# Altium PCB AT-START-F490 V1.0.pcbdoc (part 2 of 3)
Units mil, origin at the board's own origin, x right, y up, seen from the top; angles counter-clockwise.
Board outline 15424.54 x 3536.36 mil, 2 copper layers (Top Layer, Bottom Layer); 130 components, 126 nets, 528 pads, 715 vias.
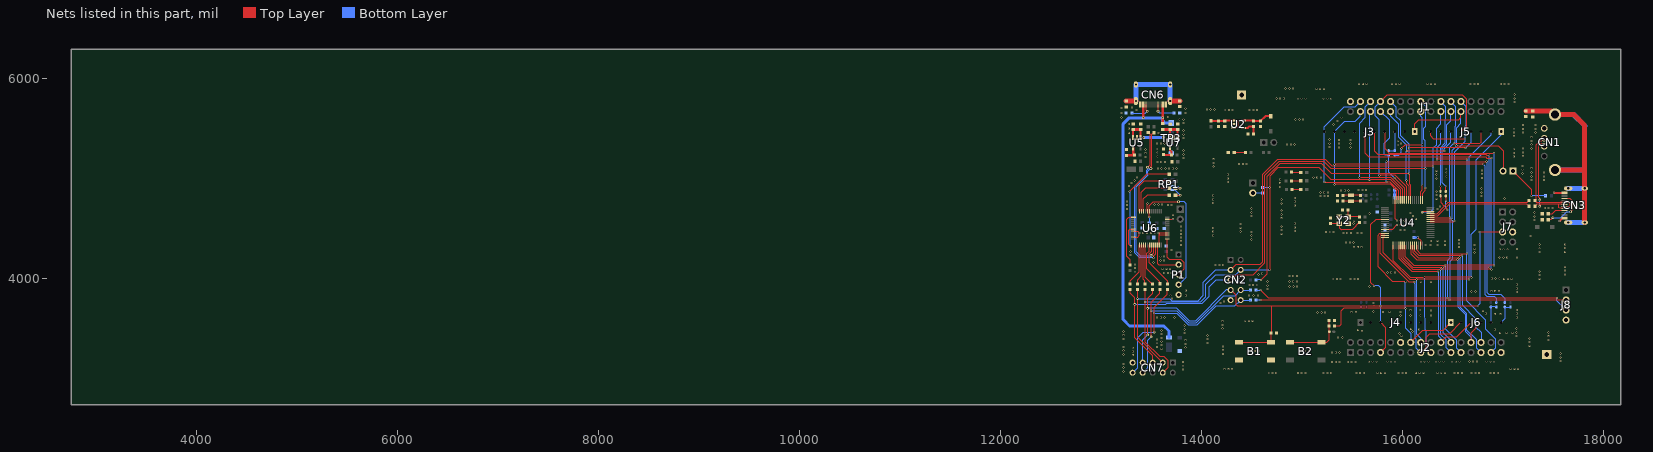
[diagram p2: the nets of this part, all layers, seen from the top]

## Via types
v1: diameter 19.68, hole 11.81, Top Layer to Bottom Layer, 622 vias
v2: diameter 19.69, hole 11.81, Top Layer to Bottom Layer, 42 vias
v3: diameter 23.62, hole 11.81, Top Layer to Bottom Layer, 17 vias
v4: diameter 27.56, hole 13.78, Top Layer to Bottom Layer, 15 vias
v5: diameter 19.7, hole 11.81, Top Layer to Bottom Layer, 10 vias
v6: diameter 24, hole 12, Top Layer to Bottom Layer, 7 vias
v7: diameter 27.56, hole 15.75, Top Layer to Bottom Layer, 2 vias

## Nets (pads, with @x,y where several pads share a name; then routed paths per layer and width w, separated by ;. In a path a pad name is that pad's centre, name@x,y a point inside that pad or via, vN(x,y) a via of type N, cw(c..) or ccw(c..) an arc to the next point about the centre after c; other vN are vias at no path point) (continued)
$1N336: LD2.1 RP1.7 | length 125.3
  Top Layer w6: LD2.1@13742.62,4903.16 13786.17,4903.16 v4(13786.58,4903.56)
  Bottom Layer w6: RP1.7@13713.41,4922.99 13767.15,4922.99 v4(13786.58,4903.56)
$1N337: LD1.1 RP1.8 | length 147.5
  Top Layer w6: LD1.1@13742.62,4833.56 v4(13790.58,4833.56)
  Bottom Layer w6: RP1.8@13713.41,4887.56 13736.58,4887.56 v4(13790.58,4833.56)
$1N361: C15.1 C16.1 C18.1 C19.1 F2.2 U5.1 U5.3 U7.1 U7.3 | length 730.4
  Top Layer w20: U5.3@13320.15,5405.9 13320.15,5484.86 C18.1@13321.15,5485.86 ; U5.1@13395.15,5405.9 C19.1@13395.15,5485.86 ; U7.3@13689.34,5407.9 C15.1@13689.34,5486.07 ; U7.1@13764.34,5407.9 C16.1@13764.34,5487.9
  Top Layer w30: C18.1@13321.15,5485.86 C19.1@13395.15,5485.86 ; F2.2@13617.56,5487.94 13689.58,5487.94 C16.1@13764.31,5487.94
  Bottom Layer w30: v4(13427.14,5405.91) 13616.74,5405.91 v4(13617.84,5407.02)
$1N396: R50.1 R51.1 U5.4 | length 160.1
  Top Layer w25: R51.1@13254.58,5231.06 13332.58,5231.06 R50.1@13335.08,5233.56 13320.15,5248.49 U5.4@13320.15,5305.9
$1N467: R43.1 R49.1 U7.4 | length 163.5
  Top Layer w20: R49.1@13616.92,5236.02 R43.1@13702.92,5236.02 13702.92,5267.02 13689.34,5280.6 U7.4@13689.34,5307.9
$2N290: C3.1 D2.1 R1.2 U2.5 | length 294.6
  Top Layer w20: U2.5@14417.58,5577.54 14513.92,5577.53 R1.2@14518.58,5572.87 C3.1@14590.58,5572.87 14638.07,5620.36 D2.1@14690.58,5620.36
$2N291: R1.1 R2.2 U2.4 | length 180.7
  Top Layer w20: U2.4@14417.58,5502.54 14462.55,5502.53 14477.89,5517.88 R1.1@14518.58,5517.87 R2.2@14518.08,5444.56
$2N326: LED1.1 R3.2 | length 110.5
  Top Layer w10: LED1.1@14328.62,5259.36 14328.83,5259.56 R3.2@14439.08,5259.56
$2N337: C1.1 C2.1 F1.2 U2.1 U2.3 | length 370.1
  Top Layer w6: U2.3@14317.58,5502.54 14346.55,5502.53 14360.58,5516.56 14360.58,5565.56 14348.6,5577.53 U2.1@14317.58,5577.54
  Top Layer w20: F1.2@14096.38,5575.88 14099.38,5572.88 C1.1@14172.58,5572.87 C2.1@14232.58,5572.87 14237.24,5577.53 U2.1@14317.58,5577.54
$2N360: B2.3 B2.4 R5.2 R6.1 R7.1 | length 593.1
  Top Layer w10: B2.4@14883.61,3367.74 14886.02,3370.14 15196.06,3370.14 15246.16,3370.14 15270.58,3394.57 15270.58,3471.68 R6.1@15273.45,3474.57 15269.08,3478.95 R5.2@15269.08,3530.57 R7.1@15269.08,3586.57
$2N488: LED3.1 R14.1 | length 90.1
  Top Layer w10: R14.1@14898.69,4976.21 14899.25,4976.77 LED3.1@14988.53,4976.77
$2N489: LED2.1 R13.1 | length 88.5
  Top Layer w10: R13.1@14900.08,4890.56 14900.3,4890.77 LED2.1@14988.53,4890.77
$2N490: LED4.1 R15.1 | length 90.4
  Top Layer w10: R15.1@14898.69,5062.21 14900.14,5060.77 LED4.1@14988.53,5060.77
$2N12490: JP2.1 R54.1 | length 462.3
  Top Layer w6: JP2.1@17103.58,5073.56 17287.58,4889.56 v1(17287.58,4827.56)
  Bottom Layer w6: v1@17286.58,4828.56 v1(17287.58,4827.56) R54.1@17426.26,4827.56
$3N199: J6.5 R34.2 R35.2 | length 211.5
  Bottom Layer w6: R34.2@16880.58,3721.16 R34.2@16881.06,3720.68 ; J6.5@16883.88,3566.57 16883.88,3717.86 R34.2@16881.06,3720.68 ; R35.2@16936.58,3720.68 R34.2@16881.06,3720.68
$3N200: J6.6 R36.2 R37.2 | length 225.1
  Bottom Layer w6: J6.6@16983.88,3566.57 17020.58,3603.26 R36.2@17020.58,3720.16 17075.97,3720.16 R37.2@17076.58,3719.57
$3N264: J3.3 R38.1 R39.1 | length 249.4
  Bottom Layer w6: R38.1@15864.58,5277.05 15923.93,5277.05 R39.1@15924.58,5277.69 15923.88,5278.39 J3.3@15923.88,5466.56
$4N238: C25.2 R26.2 Y2.3 | length 181.2
  Top Layer w6: C25.2@15460.58,4684.56 15460.58,4617.72 Y2.3@15459.89,4617.03 15460.35,4616.56 R26.2@15573.08,4616.56
$4N239: C26.2 R27.2 Y2.1 | length 366.6
  Top Layer w6: C26.2@15283.58,4549.56 15372.73,4549.56 Y2.1@15373.26,4550.1 15373.26,4511.88 15394.58,4490.56 15501.08,4490.56 R27.2@15573.08,4562.56
$4N333: C24.2 R23.2 Y1.2 | length 173.4
  Top Layer w6: C24.2@15411.08,4773.56 15412.08,4774.56 R23.2@15584.08,4774.56
$4N335: C23.2 R22.2 Y1.1 | length 171
  Top Layer w6: C23.2@15411.08,4832.56 Y1.1@15487.58,4832.56 R22.2@15582.08,4832.56
$4N462: JP1.2 R31.1 | length 99.2
  Bottom Layer w6: JP1.2@14511.57,4856.56 14610.08,4856.56 R31.1@14610.58,4856.06
ATLINK_5V: CN6.A4B9 CN6.B4A9 D3.2 F2.1 TP3.1 | length 3381.4
  Top Layer w25: v4(13421.92,5604.02) 13422.08,5604.17 CN6.B4A9@13422.08,5735.27 ; v4(13614.56,5604.02) v4@13615.03,5604.49 ; CN6.A4B9@13615.08,5735.27 13615.08,5604.49 13615.08,5549.73 F2.1@13616.58,5548.23
  Bottom Layer w30: D3.2@13676.62,3415.32 13676.58,3482.57 13626.58,3532.57 13283.81,3532.57 13220.92,3595.45 13220.92,5543.59 13281.34,5604.02 v4(13421.92,5604.02) v4(13614.56,5604.02) 13614.56,5573.39 13636.92,5551.02 TP3.1@13699.92,5551.02
ATLK_RX: CN2.10 CN7.10 R10.2 R48.1 | length 2143.2
  Top Layer w6: v3(13530.58,3470.57) v2(13530.58,3660.57) 13530.58,3718.57 13660.58,3848.57 R48.1@13660.58,3893.07
  Bottom Layer w6: CN7.10@13315.34,3067.01 13365.92,3117.59 13365.92,3416.01 13420.47,3470.57 v3(13530.58,3470.57) ; v2(13530.58,3660.57) 13752.58,3660.57 13868.58,3544.57 13960.58,3544.57 14148.58,3732.57 14333.65,3732.57 CN2.10@14390.92,3789.84 ; CN2.10@14390.97,3789.89 14391.26,3790.2 R10.2@14490.52,3790.2
ATLK_TX: CN2.8 CN7.8 R9.2 R47.1 | length 2063.7
  Top Layer w6: v3(13499.34,3423.01) 13499.34,3769.34 13586.34,3856.34 R47.1@13586.34,3886.01
  Bottom Layer w6: CN7.8@13415.35,3067.01 13463.92,3115.58 13463.92,3387.58 v3(13499.34,3423.01) ; v3(13498.58,3682.57) 13756.58,3682.57 13876.58,3562.57 13950.58,3562.57 14222.58,3834.57 14335.65,3834.57 CN2.8@14390.92,3889.84 14392.02,3888.74 R9.2@14486.73,3888.74
BOOT0/PF11: CN2.4 CN7.4 J1.28 R31.2 R45.1 U4.60 | length 5618.1
  Top Layer w6: R45.1@13438.34,3888.01 13438.34,3376.8 13583.12,3232.01 13623.92,3232.01 13665.92,3190.01 13665.92,3117.59 CN7.4@13615.34,3067.01 ; v2(14678.58,4090.57) 14678.58,5022.56 14760.58,5104.56 15174.58,5104.56 15292.58,4986.56 v1(15675.45,4986.56) 15884.58,4986.56 15984.67,4886.47 U4.60@15984.67,4787.08
  Bottom Layer w6: v3(13438.58,3770.57) 13994.58,3770.57 14044.58,3820.57 14044.58,3945.57 14141.58,4042.57 14343.65,4042.57 CN2.4@14390.92,4089.84 v2(14678.58,4090.57) ; R31.2@14610.58,4911.06 v5(14678.73,4911.06) ; v1(15675.45,4986.56) 15675.58,4986.82 15675.58,5657.99 J1.28@15683.44,5665.86
CC1: CN6.A5 R56.1 | length 231.5
  Top Layer w6: v4@13567.58,5669.56 v4(13567.77,5669.77) CN6.A5@13567.77,5735.27
  Bottom Layer w6: v4(13567.77,5669.77) 13585.98,5651.56 R56.1@13725.92,5651.56
CC2: CN6.B5 R57.1 | length 230.4
  Top Layer w6: CN6.B5@13449.67,5735.27 13449.67,5681.47 v4(13461.58,5669.56)
  Bottom Layer w6: R57.1@13309.24,5651.56 13443.58,5651.56 v4(13461.58,5669.56)
EGND: C30.2 CN1.SH1 CN1.SH2 CN3.13 CN3.14 CN3.15 CN3.16 R59.1 | length 3841.4
  Top Layer w50: C30.2@17229.58,5670.56 17485.51,5670.56 CN1.SH1@17519.93,5636.15 17706.99,5636.15 17815.88,5527.27 17815.88,5089.56 ; CN1.SH2@17519.93,5084.97 17811.28,5084.97 17815.88,5089.56 ; CN3.15@17815.88,4561.47 CN3.16@17815.88,4901.66 17815.88,5089.56
  Bottom Layer w50: CN1.SH2@17519.93,5084.97 17812.82,5084.97 17815.88,5081.92 ; CN1.SH1@17519.93,5636.15 17703.99,5636.15 17816.58,5523.56 17815.88,5522.86 17815.88,5081.92 ; CN3.13@17651.28,4561.47 CN3.15@17815.88,4561.47 CN3.16@17815.88,4901.66 ; CN3.14@17651.28,4901.66 CN3.16@17815.88,4901.66 ; CN3.16@17815.88,4901.66 17815.88,5081.92
EGND2: C29.2 CN6.13 CN6.14 CN6.15 CN6.16 R55.1 | length 863.4
  Top Layer w50: R55.1@13250.58,5771.56 13348.17,5771.56 CN6.14@13348.48,5771.27 ; CN6.13@13688.67,5771.27 13688.82,5771.12 C29.2@13784.58,5771.12
  Bottom Layer w50: CN6.14@13348.48,5771.27 CN6.16@13348.48,5935.86 CN6.15@13688.67,5935.86 CN6.13@13688.67,5771.27
FCC1: CN3.A5 R17.1 | length 176.6
  Top Layer w6: R17.1@17452.24,4649.56 17494.58,4649.56 17527.38,4682.36 CN3.A5@17615.28,4682.36
FCC2: CN3.B5 R16.1 | length 457.9
  Top Layer w6: R16.1@17453.24,4589.56 17478.58,4589.56 v6(17499.58,4610.56) ; CN3.B5@17615.28,4800.47 17669.67,4800.47 17692.58,4777.56 17692.58,4685.56 v6(17675.58,4668.56)
  Bottom Layer w6: v6(17499.58,4610.56) 17576.58,4610.56 17634.58,4668.56 v6(17675.58,4668.56)
FD+: CN1.3 CN3.A6 CN3.B6 R18.2 | length 1102.9
  Top Layer w11.2: R18.2@17321.58,4776.56 R18.2@17321.4,4776.4 ; CN1.3@17413.23,5399.94 17382.46,5369.16 17369.73,5369.16 17334.38,5333.81 17334.38,4793.36 R18.2@17321.58,4780.56 17321.4,4780.4 R18.2@17321.4,4776.4 ; CN3.A6@17615.28,4721.77 17658.78,4721.77 17666.58,4729.56 17666.58,4752.56 17658.08,4761.06 CN3.B6@17615.28,4761.06 17579.12,4761.06 17577.88,4759.81 17337.99,4759.81 R18.2@17321.4,4776.4
FD-: CN1.2 CN3.A7 CN3.B7 R19.2 | length 1109.5
  Top Layer w11.2: R19.2@17321.24,4717.56 17321.24,4724.87 17338.98,4742.61 17367.52,4742.61 ; v6(17367.52,4722.62) 17367.52,4742.61 ; v6(17367.58,4786.56) 17367.58,4804.56 17351.58,4820.56 17351.58,5326.68 17369.16,5344.27 17390.15,5344.27 CN1.2@17413.23,5321.19 ; 17559.58,4742.5 17559.58,4710.56 17568.08,4702.06 CN3.B7@17615.28,4702.06 ; CN3.A7@17615.28,4741.36 17579.12,4741.36 17577.88,4742.61 17367.52,4742.61
  Bottom Layer w11.2: v6(17367.52,4722.62) v6@17367.52,4786.51
GND: B1.3 B1.4 C1.2 C2.2 C3.2 C4.2 C5.2 C6.2 C7.2 C8.2 C9.2 C10.2 C11.2 C12.2 C13.1 C14.2 C15.2 C16.2 C17.2 C18.2 C19.2 C22.2 C23.1 C24.1 C25.1 C26.1 C27.1 C28.1 C29.1 C30.1 CN1.4 CN2.9 CN3.A1B12 CN3.B1A12 CN6.A1B12 CN6.B1A12 CN7.9 D4.2 J1.31 J2.12 J2.31 J3.7 J4.6 J4.7 J7.6 J8.4 LED1.2 P1.5 R2.1 R7.2 R16.2 R17.2 R49.2 R51.2 R55.2 R56.2 R57.2 R59.2 T1.1 T2.1 TP3.4 U2.2 U4.12 U4.31 U4.63 U5.2 U6.8 U6.20 U6.23 U6.35 U6.39 U6.40 U6.47 U7.2 Y2.2 Y2.4 | length 1321.8
  Top Layer w8: U4.63@15925.62,4787.08 15925.62,4604.52 v1(15946.58,4583.56) ; v1(16154.11,4412.03) 16181.52,4384.61 U4.31@16181.52,4334.34
  Top Layer w9: U4.12@15827.2,4491.81 15900.82,4491.81 v1(15946.58,4537.56)
  Top Layer w10: U6.23@13324.5,4417.1 13365.11,4417.1 13383.58,4435.56 v1(13383.58,4458.56) 13365.98,4476.16 U6.20@13324.5,4476.16 ; U6.8@13462.3,4673.02 13462.58,4673.3 v1(13462.58,4750.56) ; U6.35@13580.41,4338.36 13580.41,4449.2 ; U6.39@13659.15,4436.8 13592.81,4436.8 13580.41,4449.2 ; U6.40@13659.15,4456.48 13659.06,4456.56 v1(13573.04,4456.56) 13580.41,4449.2 ; U6.47@13659.15,4594.27 13717.28,4594.27 v1(13717.58,4594.56)
  Top Layer w20: v1(17508.58,4862.56) 17513.58,4857.56 17614.47,4857.56 CN3.B1A12@17615.28,4858.36 ; v1(17564.58,4575.56) 17593.58,4604.56 CN3.A1B12@17615.28,4604.56
  Bottom Layer w20: C4.2@15924.08,4884.56 15924.58,4884.06 C5.2@15924.58,4834.56 15924.58,4797.56 ; C6.2@16115.6,4414.83 16118.4,4412.03 v1(16154.11,4412.03)
  other v1: 14670.58,3064.57 14707.81,3064.57 14745.04,3064.57 14960.58,3064.57 14997.81,3064.57 15035.04,3064.57 15217.58,3064.57 15254.81,3064.57 15292.04,3064.57 15542.58,3064.57 15579.81,3064.57 15617.04,3064.57 15962.58,3064.57 15999.81,3064.57 16037.04,3064.57 16518.58,3064.57 16555.81,3064.57 16593.04,3064.57 16689.58,3064.57 16726.81,3064.57 16764.04,3064.57 16876.58,3064.57 16913.81,3064.57 16951.04,3064.57 15752.58,3065.57 15789.81,3065.57 15827.04,3065.57 16134.58,3065.57 16171.81,3065.57 16209.04,3065.57 16350.58,3065.57 16387.81,3065.57 16425.04,3065.57 13225.58,3079.57 13817.58,3098.57 14230.58,3101.57 14267.81,3101.57 14305.04,3101.57 17077.58,3105.57 17114.81,3105.57 17152.04,3105.57 13225.58,3116.8 13817.58,3135.8 13225.58,3154.03 13817.58,3173.03 15300.58,3174.57 15337.81,3174.57 15375.04,3174.57 15457.58,3174.57 15494.81,3174.57 15532.04,3174.57 15666.58,3175.57 15703.81,3175.57 15741.04,3175.57 15851.58,3175.57 15888.81,3175.57 15926.04,3175.57 16185.58,3175.57 16222.81,3175.57 16260.04,3175.57 16334.58,3175.57 16371.81,3175.57 16409.04,3175.57 16495.58,3175.57 16532.81,3175.57 16570.04,3175.57 16838.58,3175.57 16875.81,3175.57 16913.04,3175.57 16667.58,3176.57 16704.81,3176.57 16742.04,3176.57 17572.58,3182.57 17572.58,3219.8 13317.58,3240.57 13224.58,3248.57 14213.58,3253.57 17572.58,3257.03 15300.58,3268.57 15337.81,3268.57 15375.04,3268.57 13317.58,3277.8 14494.29,3281.57 14531.52,3281.57 14568.75,3281.57 14996.57,3281.56 15033.8,3281.56 15071.04,3281.56 13224.58,3285.8 14213.58,3290.8 13603.58,3304.57 13317.58,3315.03 13840.58,3315.57 13224.58,3323.03 13558.58,3322.57 14213.58,3328.03 17268.58,3334.57 13603.58,3341.8 13840.58,3352.8 13558.58,3359.8 14059.58,3363.57 17268.58,3371.8 13603.58,3379.03 13840.58,3390.03 17457.58,3393.1 13558.58,3397.03 14059.58,3400.8 13224.58,3402.57 17268.58,3409.03 13603.58,3413.57 15360.58,3417.57 15406.97,3417.57 17457.58,3430.33 17138.58,3430.57 15992.58,3433.57 14059.58,3438.03 13224.58,3439.8 13603.58,3450.8 15971.58,3455.57 13829.58,3460.57 16974.58,3463.57 17036.92,3463.57 17098.36,3463.57 17138.58,3467.8 17457.58,3467.57 13224.58,3477.03 16100.58,3477.57 15597.58,3479.57 13603.58,3488.03 15560.58,3493.57 16920.58,3497.35 13829.58,3497.8 16168.58,3498.57 16088.58,3503.57 14210.58,3504.57 17138.58,3505.03 13829.58,3535.03 14210.58,3541.8 14210.58,3579.03 14436.58,3583.57 14473.81,3583.57 14511.04,3583.57 13559.11,3616.57 13596.34,3616.57 13633.58,3616.57 13731.58,3617.57 17139.58,3617.57 15981.58,3634.57 16285.58,3635.57 16081.58,3636.57 16178.58,3636.57 16920.58,3648.57 16975.48,3648.57 17139.58,3654.8 15156.58,3664.57 15193.81,3664.57 15231.04,3664.57 15495.58,3668.57 15540.58,3668.57 15807.58,3671.57 15981.58,3672.25 15873.58,3672.57 15715.58,3674.92 16285.58,3686.21 16081.58,3688.73 16178.58,3689.83 17139.58,3692.03 15715.58,3760.57 14191.58,3761.57 14223.58,3774.57 13707.58,3807.57 13844.58,3834.9 14474.58,3836.57 14517.81,3836.57 14562.28,3836.57 13693.58,3837.57 17139.58,3868.57 16690.58,3873.57 16727.81,3873.57 16887.58,3877.57 16924.81,3877.57 16962.04,3877.57 13844.58,3886.57 14656.58,3899.57 17139.58,3905.8 14877.58,3924.57 14914.81,3924.57 14952.04,3924.57 15674.58,3925.57 14656.58,3936.8 14476.58,3939.57 14513.81,3939.57 14551.04,3939.57 17139.58,3943.03 16183.58,3971.57 16286.58,3971.57 14656.58,3974.03 14876.58,3974.57 14913.81,3974.57 14951.04,3974.57 15312.58,4000.57 15349.81,4000.57 15387.04,4000.57 15484.58,4000.57 15521.81,4000.57 15559.04,4000.57 17363.58,4001.1 17014.11,4001.57 17051.34,4001.57 17088.58,4001.57 16890.58,4003.57 16927.81,4003.57 16965.04,4003.57 14876.58,4030.57 14913.81,4030.57 14951.04,4030.57 17363.58,4038.33 14569.58,4042.57 17619.58,4046.1 14605.58,4054.57 13630.11,4059.57 13667.34,4059.57 13704.58,4059.57 15851.89,4065.14 15889.12,4065.14 15926.35,4065.14 13339.58,4071.57 17363.58,4075.57 17619.58,4083.33 13613.11,4100.56 13650.34,4100.56 13687.58,4100.56 13339.58,4108.8 17619.58,4120.56 14142.58,4137.56 14179.81,4137.56 14217.04,4137.56 13339.58,4146.03 13524.58,4164.56 13593.58,4183.56 13627.58,4183.56 16969.58,4215.56 17006.81,4215.56 17044.04,4215.56 17142.58,4215.56 13593.58,4220.8 13627.58,4221.63 13294.58,4237.56 16717.58,4262.33 17363.58,4268.1 17621.58,4270.1 13294.58,4272.69 13703.58,4289.56 16970.58,4295.56 17007.81,4295.56 17045.04,4295.56 17142.58,4296.56 16717.58,4299.56 17363.58,4305.33 17621.58,4307.33 15519.58,4315.56 15556.81,4315.56 15594.04,4315.56 16564.58,4318.33 16281.58,4336.56 16348.58,4336.96 16426.58,4336.56 16717.58,4336.8 13797.58,4338.56 16228.58,4338.56 17363.58,4342.56 17621.58,4344.56 16564.58,4352.56 15440.58,4362.56 15477.81,4362.56 15515.04,4362.56 13797.58,4375.8 16283.58,4378.56 16426.58,4379.17 16348.58,4379.56 16564.58,4387.8 14500.58,4393.56 13797.58,4413.03 17274.58,4427.56 14500.58,4430.8 14117.58,4432.56 13796.58,4446.56 14795.58,4449.56 13498.58,4456.56 13535.81,4456.56 15414.58,4456.56 15451.81,4456.56 15489.04,4456.56 13420.81,4458.56 13458.04,4458.56 14500.58,4468.03 15240.58,4468.56 15277.81,4468.56 15315.04,4468.56 14117.58,4469.8 14387.58,4471.56 14929.58,4476.56 13796.58,4483.8 14795.58,4486.8 14117.58,4507.03 14387.58,4508.8 14929.58,4513.8 13796.58,4521.03 14795.58,4524.03 15983.81,4537.56 16021.04,4537.56 14387.58,4546.03 14929.58,4551.03 15983.81,4583.56 16021.04,4583.56 17317.58,4586.56 16134.58,4598.56 14795.58,4604.56 17317.58,4623.8 14500.58,4625.56 16105.58,4625.56 13717.58,4638.57 14795.58,4641.8 16083.58,4655.56 17317.58,4661.03 14500.58,4662.8 14795.58,4679.03 13258.58,4697.56 16350.58,4697.56 14500.58,4700.03 17418.58,4706.56 17455.81,4706.56 17493.04,4706.56 16375.58,4722.56 14929.58,4732.56 13258.58,4734.8 13668.58,4735.56 13703.67,4735.56 13534.58,4741.56 13571.81,4741.56 13609.04,4741.56 14795.58,4752.56 14117.58,4754.56 14929.58,4769.8 13258.58,4772.03 14795.58,4789.8 14117.58,4791.8 16338.58,4797.56 17018.04,4799.56 14929.58,4807.03 16790.58,4825.33 15186.58,4825.56 15223.81,4825.56 15261.04,4825.56 14117.58,4829.03 16338.58,4834.8 15185.58,4859.56 15222.81,4859.56 15260.04,4859.56 16790.58,4862.56 16338.58,4872.03 15390.58,4881.56 15427.81,4881.56 15465.04,4881.56 15564.58,4885.56 15601.81,4885.56 15639.04,4885.56 16790.58,4899.8 14784.58,4915.56 13278.58,4926.56 14784.58,4952.8 13305.58,4953.56 14262.58,4964.56 13332.58,4979.56 17286.58,4983.56 17410.58,4984.56 14784.58,4990.03 14262.58,5001.8 16342.58,5001.56 16792.58,5005.33 13357.58,5007.56 15115.58,5011.56 15152.81,5011.56 15190.04,5011.56 16437.58,5020.56 17286.58,5020.8 17410.58,5021.8 14262.58,5039.03 16342.58,5038.8 16792.58,5042.56 17196.58,5049.56 16437.58,5057.8 17286.58,5058.03 17410.58,5059.03 16342.58,5076.03 16792.58,5079.8 17196.58,5086.8 16437.58,5095.03 13567.58,5098.56 13604.81,5098.56 13642.04,5099.56 13678.58,5099.56 13715.81,5099.56 13753.04,5099.56 17286.58,5102.56 14118.58,5117.56 17196.58,5124.03 14375.58,5143.56 14412.81,5143.56 14450.04,5143.56 14118.58,5154.8 13562.58,5163.56 13599.81,5163.56 13637.04,5163.56 14118.58,5192.03 13821.58,5202.56 13444.58,5214.56 17109.58,5216.56 13560.58,5219.56 17201.58,5221.56 13821.58,5239.8 13444.58,5251.8 17109.58,5253.8 13560.58,5256.8 17201.58,5258.8 13821.58,5277.03 13444.58,5289.03 17109.58,5291.03 13560.58,5294.03 17201.58,5296.03 17286.58,5297.03 15370.58,5309.56 15483.58,5309.56 15276.58,5312.56 15959.58,5334.56 17286.58,5336.56 14853.58,5338.56 14890.81,5338.56 14928.04,5338.56 15370.58,5346.8 15483.58,5346.8 15987.58,5347.56 13559.58,5348.56 13596.81,5348.56 13634.04,5348.56 15276.58,5349.8 17286.58,5373.8 15959.58,5375.29 15370.58,5384.03 15483.58,5384.03 15276.58,5387.03 13820.58,5402.56 17286.58,5411.03 17110.58,5420.56 13820.58,5439.8 13572.58,5451.56 13277.58,5454.56 17202.58,5456.56 17324.58,5456.56 17110.58,5457.8 13820.58,5477.03 17202.58,5493.8 17324.58,5493.8 17110.58,5495.03 13277.58,5499.09 17202.58,5531.03 17324.58,5531.03 15313.58,5537.56 13277.19,5541.35 13821.58,5551.56 15356.58,5571.56 14938.58,5587.56 14975.81,5587.56 15013.04,5587.56 13779.58,5588.56 13821.58,5588.8 15395.58,5604.56 13204.58,5605.56 13669.58,5611.56 13840.57,5651.57 13204.58,5652.69 14480.58,5680.56 14517.81,5680.56 14555.04,5680.56 13355.58,5681.56 14237.58,5682.56 14274.81,5682.56 14312.04,5682.56 14054.58,5686.56 14091.81,5686.56 14129.04,5686.56 13840.57,5698.23 13203.58,5701.56 13309.79,5706.25 17114.58,5760.56 14960.58,5793.56 14997.81,5793.56 15035.04,5793.56 15217.58,5793.56 15254.81,5793.56 15292.04,5793.56 14745.58,5795.56 14782.81,5795.56 14820.04,5795.56 17114.58,5797.8 17114.58,5835.03 15144.58,5892.56 15181.81,5892.56 15219.04,5892.56 14838.58,5895.56 14875.81,5895.56 14913.04,5895.56 16680.58,5940.56 16717.81,5940.56 16755.04,5940.56 16980.58,5940.56 17017.81,5940.56 17055.04,5940.56 15569.58,5942.56 15606.81,5942.56 15644.04,5942.56 15898.58,5942.56 15935.81,5942.56 15973.04,5942.56 16249.58,5942.56 16286.81,5942.56 16324.04,5942.56
  other v5: 16831.58,3654.57 16803.58,3682.57 15553.58,4456.56 15595.31,4456.56 15981.58,4485.56 16020.01,4485.56 15514.58,4550.56 15521.58,4578.56 15671.58,4650.56
LD1: LD1.2 U6.10 | length 397.2
  Top Layer w6: U6.10@13422.92,4673.02 13422.92,4795.91 13460.58,4833.56 LD1.2@13681.62,4833.56
LD2: LD2.2 U6.11 | length 485.7
  Top Layer w6: U6.11@13403.24,4673.02 13403.24,4864.23 13442.17,4903.16 LD2.2@13681.62,4903.16
LD3: LD3.2 U6.12 | length 585.9
  Top Layer w6: U6.12@13383.56,4673.02 13383.56,4928.55 13427.58,4972.56 LD3.2@13681.42,4972.56 ; LD3.2@13681.62,4972.76 LD3.2@13681.42,4972.56 ; LD3.2@13695.42,4972.56 LD3.2@13681.42,4972.56
LD4: LD4.2 U6.19 | length 1244
  Top Layer w6: v1(13286.58,4872.56) 13456.37,5042.36 LD4.2@13681.62,5042.36 ; v3(13298.92,4324.02) 13275.92,4347.02 13275.92,4487.02 13284.76,4495.85 U6.19@13324.5,4495.85
  Bottom Layer w6: v1(13286.58,4872.56) 13286.34,4872.34 13286.34,4336.6 v3(13298.92,4324.02)
M-ATLK_RX: R48.2 U6.31 | length 479.5
  Top Layer w6: U6.31@13501.67,4338.36 13501.67,4272.34 13474.58,4245.24 13474.58,4165.44 13660.34,3979.68 R48.2@13660.34,3947.01
M-ATLK_TX: R47.2 U6.30 | length 454
  Top Layer w6: U6.30@13481.98,4338.36 13481.98,4276.65 13458.58,4253.24 13458.58,4099.26 13586.34,3971.49 R47.2@13586.34,3947.01
M-NRST: C22.1 P1.4 U6.7 | length 1403.3
  Top Layer w6: v3(13480.85,4617.02) 13481.98,4618.15 U6.7@13481.98,4673.02 ; U6.7@13480.85,4674.15 U6.7@13481.98,4673.02 ; v4(13772.23,4769.02) 13521.02,4769.02 13481.98,4729.97 U6.7@13481.98,4673.02
  Bottom Layer w6: C22.1@13480.58,4558.12 13480.85,4558.4 C22.1@13480.85,4561.35 ; v3(13480.85,4617.02) C22.1@13480.85,4561.35 ; C22.1@13481.15,4561.06 C22.1@13480.85,4561.35 ; v4(13772.23,4769.02) 13827.93,4769.02 13848.93,4748.02 13848.93,4018.92 P1.4@13772.58,3942.57
M-SWCLK: P1.3 U6.37 | length 518.8
  Top Layer w6: U6.37@13659.15,4397.43 13659.15,4213.99 13682.58,4190.56 13801.58,4190.56 13829.58,4162.56 13829.58,4099.56 P1.3@13772.58,4042.57
M-SWDIO: P1.2 U6.34 | length 398.8
  Top Layer w6: U6.34@13560.72,4338.36 13560.72,4157.65 13575.8,4142.56 P1.2@13772.58,4142.56
M-USB_D+: R11.2 U6.33 | length 1619.6
  Top Layer w11.2: v4(13464.58,5111.56) 13490.48,5137.47 13490.48,5438.53 R11.2@13469.58,5459.43 ; v3(13523.58,4211.56) 13523.58,4231.19 13539.79,4247.4 13539.79,4303.9 13541.03,4305.14 U6.33@13541.03,4338.36
  Bottom Layer w11.2: v4(13464.58,5111.56) 13464.58,5090.89 13450.8,5077.11 13450.8,5039.01 13330.58,4918.79 13330.58,4266.44 13387.83,4209.19 13521.2,4209.19 v3(13523.58,4211.56)
M-USB_D-: R12.2 U6.32 | length 1549.3
  Top Layer w11.2: v4(13497.58,5099.56) 13497.58,5116.25 13507.67,5126.35 13507.67,5438.53 R12.2@13528.58,5459.43 ; v3(13499.58,4234.56) 13522.59,4257.58 13522.59,4303.9 13521.34,4305.14 U6.32@13521.34,4338.36
  Bottom Layer w11.2: v4(13497.58,5099.56) 13468,5069.99 13468,5031.88 13347.77,4911.66 13347.77,4273.56 13394.95,4226.39 13491.4,4226.39 v3(13499.58,4234.56)
M_ATLK_BOOT0: R45.2 U6.27 | length 395.7
  Top Layer w6: U6.27@13422.92,4338.36 13422.92,3999.14 13438.34,3983.72 R45.2@13438.34,3949.01
M_ATLK_NRST: R46.2 U6.28 | length 419.2
  Top Layer w6: U6.28@13442.6,4338.36 13442.6,4017.76 R46.2@13512.34,3948.01
M_ATLK_SWCLK: R41.2 U6.25 | length 427
  Top Layer w6: R41.2@13290.34,3950.01 13290.34,3979.43 13383.56,4072.64 U6.25@13383.56,4338.36
M_ATLK_SWDIO: R44.2 U6.26 | length 404.5
  Top Layer w6: R44.2@13364.34,3950.01 13364.34,3993.43 13403.24,4032.32 U6.26@13403.24,4338.36
M_ATLK_SWO: R52.2 U6.13 | length 541.5
  Top Layer w6: R52.2@13290.15,4142.98 13290.15,4192.8 13255.92,4227.02 13255.92,4593.02 13276.88,4613.97 U6.13@13324.5,4613.97
NRST: B1.1 B1.2 C13.2 CN2.7 CN7.7 J2.7 J4.3 J7.5 R46.1 U4.7 | length 7579.7
  Top Layer w6: v3(13464.58,3442.57) v3(13464.58,3706.57) 13464.58,3806.57 13514.58,3856.57 13514.58,3889.24 R46.1@13512.34,3887.01 ; CN2.7@14290.92,3889.84 14340.58,3840.2 14340.58,3746.57 14356.58,3730.57 14688.08,3730.57 ; B1.1@14374.58,3368.57 B1.2@14689.58,3368.57 ; B1.2@14699.53,3366.57 14697.53,3368.57 B1.2@14689.58,3368.57 ; 15718.58,3731.62 15718.02,3731.07 ; v1(15718.58,3931.73) 15682.95,3967.35 15682.95,4539.72 15733.87,4590.64 15796.85,4590.64 15797.25,4590.24 U4.7@15827.2,4590.24 ; J2.7@15783.88,3268.14 15834.58,3318.84 15834.58,3515.86 J4.3@15783.86,3566.56 ; v1@16756.08,3731.07 v1(15784.48,3731.07) 15718.02,3731.07 ; v2(16770.58,4467.56) 16998.47,4467.56 J7.5@16998.88,4467.16 ; 14688.08,3730.57 14693.08,3725.57 ; 14688.08,3730.57 14693.08,3731.07 ; B1.2@14689.58,3368.57 14693.08,3372.07 C13.2@14693.08,3460.57 14693.08,3725.57 ; 14693.08,3725.57 14693.08,3731.07 ; 14693.08,3731.07 15718.02,3731.07
  Bottom Layer w6: CN7.7@13415.35,3167.01 13415.35,3393.34 v3(13464.58,3442.57) ; v3(13464.58,3706.57) 13756.58,3706.57 13884.58,3578.57 13936.58,3578.57 14247.85,3889.84 CN2.7@14290.92,3889.84 ; v1(15718.58,3931.73) 15763.65,3931.73 15784.48,3910.9 v1(15784.48,3731.07) ; v1@15783.58,3731.57 15783.86,3731.28 J4.3@15783.86,3566.56 ; v1(16750.95,3731.07) 16770.58,3750.69 v2(16770.58,4467.56)
PA0: J2.14 J6.1 R5.1 U4.14 | length 2690.6
  Top Layer w6: R5.1@15324.08,3530.57 15374.58,3530.57 15388.58,3544.57 15388.58,3678.57 15416.17,3706.16 v1(16030.58,3706.16) ; U4.14@15827.2,4452.44 15776.33,4452.44 15758.25,4434.35 15758.25,4119.01 15905.69,3971.57 v1(16030.58,3971.57) ; J2.14@16083.88,3368.14 16200.3,3484.57 16401.88,3484.57 J6.1@16483.88,3566.57
  Bottom Layer w6: v1(16030.58,3971.57) v1(16030.58,3706.16) 16030.58,3512.82 16083.88,3459.52 J2.14@16083.88,3368.14
PA1: J2.15 J6.2 U4.15 | length 1994.6
  Top Layer w6: U4.15@15827.2,4432.76 15781.82,4432.76 15775.82,4426.76 15775.82,4258.32 16063.58,3970.57 v1(16120.58,3970.57) ; J2.15@16183.88,3268.14 16232.58,3316.84 16232.58,3412.57 16270.58,3450.57 16467.88,3450.57 J6.2@16583.88,3566.57
  Bottom Layer w6: v1(16120.58,3970.57) 16120.58,3957.34 16125.58,3952.34 16125.58,3415.57 16134.58,3406.57 16134.58,3317.43 J2.15@16183.88,3268.14
PA2: J2.16 J5.2 U4.16 | length 3351.3
  Top Layer w6: U4.16@15827.2,4413.07 15803.34,4413.07 15803.34,4266.8 16075.58,3994.57 v1(16140.38,3994.57) v1(16664.58,3994.57)
  Bottom Layer w6: v1@16140.58,3994.57 16140.58,3454.57 16183.88,3411.26 J2.16@16183.88,3368.14 ; v1(16664.58,3994.57) 16664.58,5217.56 16883.88,5436.86 J5.2@16883.88,5466.56
PA3: J2.17 J5.1 U4.17 | length 3347
  Top Layer w6: U4.17@15905.93,4334.34 15905.93,4188.21 16078.58,4015.57 v2(16218.58,4015.57) v1(16686.78,4015.57)
  Bottom Layer w6: v2(16218.58,4015.57) 16218.58,3617.03 16224.58,3611.03 16224.58,3499.4 16234.58,3489.4 16234.58,3317.43 J2.17@16283.88,3268.14 ; v1(16686.78,4015.57) 16686.78,4445.77 16737.58,4496.56 16737.58,5188.56 16983.88,5434.86 J5.1@16983.88,5466.56
PA4: J2.20 J6.3 U4.20 | length 1674.8
  Top Layer w6: U4.20@15964.99,4334.34 15964.99,4205.15 16094.58,4075.57 v2(16355.58,4075.57) ; J2.20@16383.88,3368.14 16438.29,3422.57 16539.88,3422.57 J6.3@16683.88,3566.57
  Bottom Layer w6: v2(16355.58,4075.57) 16355.58,3435.57 16382.58,3408.57 16382.58,3369.43 J2.20@16383.88,3368.14
PA5: J2.21 J3.6 U4.21 | length 4547.2
  Top Layer w6: J3.6@15623.88,5466.56 15623.88,5257.27 15664.58,5216.56 16828.58,5216.56 16842.58,5202.56 16887.21,5202.56 v1(16887.58,5202.93) ; U4.21@15984.67,4334.34 15984.67,4212.79 16101.9,4095.57 v2(16378.58,4095.57) v1(16887.58,4095.57)
  Bottom Layer w6: v2(16378.58,4095.57) 16378.58,3450.57 16430.58,3398.57 16430.58,3321.43 J2.21@16483.88,3268.14 ; v1(16887.58,4095.57) v1(16887.58,5202.93)
PA6: J2.22 J3.5 U4.22 | length 4267.8
  Top Layer w6: J3.5@15723.88,5466.56 15723.88,5273.27 15762.58,5234.56 16835.76,5234.56 16843.6,5226.72 v1(16865.58,5226.72) ; U4.22@16004.36,4334.34 16004.36,4216.47 16105.27,4115.56 v2(16401.58,4115.56) v1(16865.58,4115.56)
  Bottom Layer w6: v2(16401.58,4115.56) 16401.58,3469.57 16483.88,3387.26 J2.22@16483.88,3368.14 ; v1(16865.58,4115.56) v1(16865.58,5226.72)
PA7: J2.23 J3.4 U4.23 | length 4357.8
  Top Layer w6: J3.4@15823.88,5466.56 15823.88,5299.27 15871.58,5251.56 v1(16911.58,5251.56) ; U4.23@16024.04,4334.34 16024.04,4225.54 16115.02,4134.56 v2(16425.58,4134.56) v1(16911.58,4134.56)
  Bottom Layer w6: v2(16425.58,4134.56) 16425.58,3503.72 16534.58,3394.72 16534.58,3317.43 J2.23@16583.88,3268.14 ; v1(16911.58,4134.56) v1(16911.58,5251.56)
PA8: J1.9 J5.8 U4.41 | length 1899.5
  Top Layer w6: U4.41@16279.94,4570.55 16514.56,4570.55 v2(16521.58,4577.56) ; J5.8@16283.88,5466.56 16283.88,5423.27 16314.58,5392.56 v2(16626.58,5392.56)
  Bottom Layer w6: v2(16521.58,4577.56) 16521.58,5266.56 16626.58,5371.56 v2(16626.58,5392.56) 16626.58,5521.05 16634.58,5529.05 16634.58,5714.73 J1.9@16583.44,5765.86
PA9: J1.10 J3.1 J8.2 JP2.2 R10.1 U4.42 | length 6533.7
  Top Layer w6: v1(14589.38,3790.76) v1(16471.38,3790.76) 17630.54,3790.76 J8.2@17630.74,3790.57 ; J3.1@16123.88,5466.56 16123.88,5545.86 16162.58,5584.56 16560.58,5584.56 16583.44,5607.44 J1.10@16583.44,5665.86 ; U4.42@16279.94,4590.24 16494.25,4590.24 v2(16496.58,4592.56) ; v1(16540.58,5326.56) 16953.58,5326.56 17003.58,5276.56 JP2.2@17003.58,5073.56
  Bottom Layer w6: R10.1@14545.77,3790.76 v1(14589.38,3790.76) ; v1(16471.38,3790.76) 16471.58,3790.97 16471.58,4169.56 16496.58,4194.56 v2(16496.58,4592.56) 16496.58,5282.56 v1(16540.58,5326.56) 16540.58,5504.56 16583.44,5547.44 J1.10@16583.44,5665.86
PA10: J1.11 J5.3 J8.3 R9.1 U4.43 | length 5771
  Top Layer w6: v1(14589.38,3888.76) 14668.58,3809.57 v1(16449.58,3809.62) v1(17539.58,3809.57) ; U4.43@16279.94,4609.92 16473.93,4609.92 v2(16474.58,4610.56) ; v2(16514.58,5348.56) 16772.58,5348.56 16783.88,5359.86 J5.3@16783.88,5466.56
  Bottom Layer w6: R9.1@14545.77,3888.76 v1(14589.38,3888.76) v1@14589.58,3888.57 ; v1(16449.58,3809.62) 16449.58,4179.56 16474.58,4204.56 v2(16474.58,4610.56) 16474.58,5308.56 v2(16514.58,5348.56) 16526.58,5360.56 16526.58,5518.44 16533.58,5525.44 16533.58,5715.73 J1.11@16483.44,5765.86 ; v1(17539.58,3809.57) 17539.58,3781.73 J8.3@17630.74,3690.57
PA11: R19.1 R32.2 U4.44 | length 1213.6
  Top Layer w6: 16432.03,4707.7 16432.03,4707.11 v1(16451.58,4687.56) ; v1(16433.58,4777.56) R32.2@16433.58,4827.16
  Top Layer w11.2: U4.44@16279.94,4629.61 16353.94,4629.61 16432.03,4707.7 16467.9,4743.56 17239.92,4743.56 R19.1@17261.92,4721.56
  Bottom Layer w6: v1(16433.58,4777.56) 16433.58,4705.56 v1(16451.58,4687.56)
PA11_E: J1.12 R32.1 | length 844.8
  Top Layer w6: R32.1@16433.58,4871.56 v1(16433.58,4922.56)
  Bottom Layer w6: v1(16433.58,4922.56) 16397.58,4958.56 16397.58,5300.56 16442.58,5345.56 16442.58,5533.56 16483.44,5574.44 J1.12@16483.44,5665.86
PA12: R18.1 R33.2 U4.45 | length 1158.4
  Top Layer w6: R33.2@16380.58,4827.56 16380.58,4761.16 16419.67,4722.06
  Top Layer w11.2: U4.45@16279.94,4649.29 16346.9,4649.29 16419.67,4722.06 16459.18,4761.56 17241.66,4761.56 17260.66,4780.56 R18.1@17262.26,4780.56
PA12_E: J1.13 R33.1 | length 937.4
  Top Layer w6: R33.1@16380.58,4871.97 v1(16380.58,4922.56)
  Bottom Layer w6: v1(16380.58,4922.56) 16380.58,5307.56 16426.58,5353.56 16426.58,5584.56 16434.58,5592.56 16434.58,5714.73 J1.13@16383.44,5765.86
PA13/SWDIO: CN2.3 CN7.3 J1.14 R44.1 U4.46 | length 6180.6
  Top Layer w6: R44.1@13364.34,3889.01 13364.34,3804.8 v3(13364.58,3804.57) 13364.58,3417.78 CN7.3@13615.34,3167.01 ; CN2.3@14290.92,4089.84 14343.65,4142.56 14581.58,4142.56 14604.58,4165.56 14604.58,5036.56 14756.58,5188.56 15235.58,5188.56 15303.58,5120.56 v2(16306.58,5120.56) ; v6(16197.12,4664.98) 16201.11,4668.98 U4.46@16279.94,4668.98
  Bottom Layer w6: v3(13364.58,3804.57) 13682.58,3804.57 13702.58,3784.57 13966.58,3784.57 14020.58,3838.57 14020.58,3965.57 14144.85,4089.84 CN2.3@14290.92,4089.84 ; v6(16197.12,4664.98) 16201.11,4668.98 16282.2,4668.98 16305.78,4692.56 16305.78,5119.77 v2(16306.58,5120.56) 16306.58,5303.56 16340.58,5337.56 16340.58,5499.56 16383.44,5542.44 J1.14@16383.44,5665.86
PA14/SWCLK: CN2.5 CN7.5 J1.17 R41.1 U4.49 | length 5919
  Top Layer w6: R41.1@13290.34,3889.01 13290.34,3858.8 13336.58,3812.57 v3(13336.58,3746.57) 13336.58,3413.57 13515.34,3234.8 CN7.5@13515.34,3167.01 ; CN2.5@14290.92,3989.84 14297.85,3989.84 14346.58,4038.57 14509.58,4038.57 14626.58,4155.56 14626.58,5026.56 14768.58,5168.56 15221.58,5168.56 15291.58,5098.56 v2(16230.58,5098.56) ; U4.49@16201.21,4787.08 16201.21,4853.03 16230.58,4882.39 v2(16230.58,4906.56)
  Bottom Layer w6: v3(13336.58,3746.57) 13644.58,3746.57 13654.58,3756.57 14010.58,3756.57 14079.58,3825.57 14079.58,3921.57 14147.85,3989.84 CN2.5@14290.92,3989.84 ; J1.17@16183.44,5765.86 16232.58,5716.73 16232.58,5517.56 16214.58,5499.56 16214.58,5389.27 16230.58,5373.27 v2(16230.58,5098.56) v2(16230.58,4906.56)
PA15: J1.18 R39.2 U4.50 | length 1231
  Top Layer w6: v2(15991.58,5298.56) 16030.58,5337.56 v2(16198.58,5337.56) ; U4.50@16181.52,4787.08 16181.52,4870.08 16198.58,4887.13 v2(16198.58,4932.56)
  Bottom Layer w6: R39.2@15924.58,5233.28 15963.3,5233.28 15991.58,5261.56 v2(15991.58,5298.56) ; J1.18@16183.44,5665.86 16183.44,5621.69 16198.58,5606.56 v2(16198.58,5337.56) v2(16198.58,4932.56)
PB0: J2.26 J6.4 U4.26 | length 1694
  Top Layer w6: U4.26@16083.1,4334.34 16083.1,4251.85 16142.39,4192.56 v2(16550.58,4192.56) ; J2.26@16683.88,3368.14 16683.88,3466.55 J6.4@16783.88,3566.57
  Bottom Layer w6: v2(16550.58,4192.56) 16550.58,3721.57 16624.58,3647.57 16624.58,3477.57 16683.88,3418.26 J2.26@16683.88,3368.14
PB1: J2.27 U4.27 | length 1590.9
  Top Layer w6: U4.27@16102.78,4334.34 16102.78,4266.31 16156.53,4212.56 v2(16570.58,4212.56)
  Bottom Layer w6: v2(16570.58,4212.56) 16570.58,3724.57 16637.58,3657.57 16637.58,3494.57 16734.58,3397.57 16734.58,3317.43 J2.27@16783.88,3268.14
PB2: J2.28 U4.28 | length 1491.6
  Top Layer w6: U4.28@16122.47,4334.34 16122.47,4276.5 16166.41,4232.56 v1(16595.64,4232.56)
  Bottom Layer w6: v1(16595.64,4232.56) 16595.58,3741.57 16727.58,3609.57 16727.58,3526.14 16783.87,3469.86 J2.28@16783.88,3368.14
PB3: J1.23 J5.4 R8.1 U4.55 | length 4416.6
  Top Layer w6: v2(14594.58,3990.57) 14654.58,4050.57 14654.58,5022.56 14782.58,5150.56 15192.58,5150.56 15291.58,5051.56 16068.58,5051.56 16068.58,4949.23 16080.59,4937.22 16080.59,4789.59 U4.55@16083.1,4787.08 ; v1(16068.58,5304.71) v1(16629.75,5304.74)
  Bottom Layer w6: R8.1@14549.73,3990.74 v2(14594.58,3990.57) ; J1.23@15883.44,5765.86 15938.58,5710.73 15938.58,5616.56 15982.58,5572.56 15982.58,5424.56 16068.58,5338.56 v1(16068.58,5304.71) v1(16068.58,5051.53) ; v1(16629.75,5304.74) 16683.88,5358.86 J5.4@16683.88,5466.56
PB4: J1.24 J5.6 U4.56 | length 1550.1
  Top Layer w6: v2(16041.18,4978.34) 16041.18,4951.86 16063.41,4929.63 U4.56@16063.41,4787.08 ; v1(16045.58,5273.65) 16418.49,5273.65 v1(16418.58,5273.56)
  Bottom Layer w6: J1.24@15883.44,5665.86 15883.44,5620.69 15966.58,5537.56 15966.58,5410.56 16045.58,5331.56 v1(16045.58,5273.65) 16041.18,5269.25 v2(16041.18,4978.34) ; v1(16418.58,5273.56) 16418.58,5294.74 16483.88,5360.05 J5.6@16483.88,5466.56
PB5: J1.25 J5.5 U4.57 | length 2465.4
  Top Layer w6: v1(15771.58,5031.56) 15930.58,5031.56 16043.73,4918.41 U4.57@16043.73,4787.08 ; J1.25@15783.44,5765.86 15850.15,5832.56 16596.58,5832.56 16634.58,5794.56 16634.58,5517.27 J5.5@16583.88,5466.56
  Bottom Layer w6: v1(15771.58,5031.56) 15771.58,5586.56 15732.58,5625.56 15732.58,5714.99 J1.25@15783.44,5765.86
PB6: J1.26 R38.2 U4.58 | length 1044.4
  Top Layer w6: v1(15920.58,5005.56) 16024.04,4902.1 U4.58@16024.04,4787.08
  Bottom Layer w6: J1.26@15783.44,5665.86 15786.27,5665.86 15872.58,5579.56 15872.58,5406.56 15818.58,5352.56 15818.58,5241.56 15831.18,5228.96 15864.58,5228.96 15864.58,5061.56 v1(15920.58,5005.56)
PB7: J1.27 U4.59 | length 1382.1
  Top Layer w6: v2(15575.58,5010.56) 15884.58,5010.56 16004.36,4890.78 U4.59@16004.36,4787.08
  Bottom Layer w6: v2(15575.58,5010.56) 15575.58,5550.56 15632.58,5607.56 15632.58,5714.99 J1.27@15683.44,5765.86
PB8: J1.29 J3.10 R36.1 U4.61 | length 4638.4
  Top Layer w6: v1(15224.58,4963.56) v1(15840.36,4963.56) 15881.58,4963.56 15964.99,4880.15 U4.61@15964.99,4787.08 ; v1(15840.36,5168.56) v2(16839.58,5168.56)
  Bottom Layer w6: v1(15224.58,4963.56) 15224.58,5465.86 J3.10@15223.88,5466.56 15223.88,5515.86 15422.58,5714.56 15532.15,5714.56 J1.29@15583.44,5765.86 ; v1(15840.36,4963.56) v1(15840.36,5168.56) ; v2(16839.58,5168.56) 16839.58,3867.57 16859.58,3847.57 16981.58,3847.57 17020.58,3808.57 R36.1@17020.58,3764.57
PB9: J1.30 J3.9 R35.1 U4.62 | length 4589.6
  Top Layer w6: v1@15323.58,5141.57 v1(16805.68,5141.57) ; v1(15323.88,4939.86) 15324.58,4940.56 15882.58,4940.56 15945.3,4877.84 U4.62@15945.3,4787.08
  Bottom Layer w6: v1(15323.88,4939.86) v1(15323.88,5141.39) J3.9@15323.88,5465.56 ; J3.9@15323.88,5466.56 15424.88,5567.56 15533.58,5567.56 15583.44,5617.44 J1.30@15583.44,5665.86 ; v1(16805.68,5141.57) 16821.58,5125.68 16821.58,3848.57 16841.58,3828.57 16913.58,3828.57 16936.58,3805.57 R35.1@16936.58,3765.08
PB10: J2.29 J5.7 U4.29 | length 3211
  Top Layer w6: U4.29@16142.15,4334.34 16142.15,4288.97 16178.25,4252.87 16642.27,4252.87 v1(16642.58,4252.56) ; v1(16346.58,5189.56) v1(16642.58,5189.56)
  Bottom Layer w6: v1(16346.58,5189.56) 16346.58,5310.56 16383.88,5347.86 J5.7@16383.88,5466.56 ; v1(16642.58,5189.56) v1(16642.58,4252.56) 16642.58,3780.57 16832.58,3590.57 16832.58,3500.57 16932.58,3400.57 16932.58,3316.84 J2.29@16883.88,3268.14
